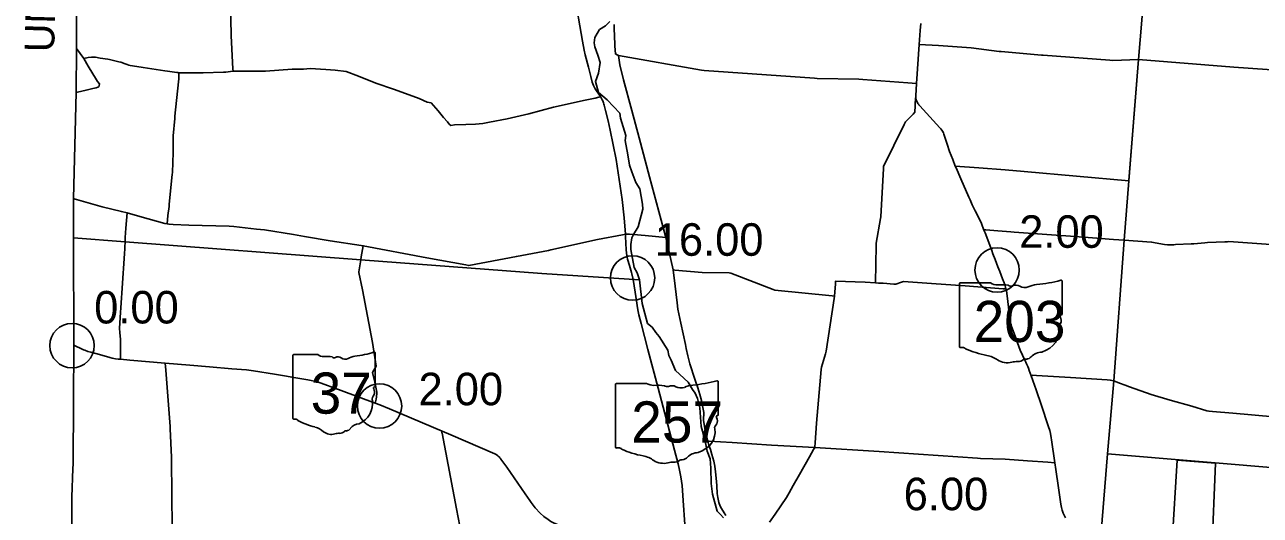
# Model space of a CAD drawing. Extents: x 1597222 to 1925846, y 496284 to 911751.
# Drawn here: x 1757865 to 1799698, y 847184 to 863780 of the extents above; entities that cross this region are included whole.
import ezdxf

# ---------------------------------------------------------------- set-up
doc = ezdxf.new("R2010")
doc.units = 0
for name, color, linetype in [('Default', 7, 'Continuous'), ('GM_X_Adjacent_County_Text', 7, 'Continuous'), ('GM_X_Corporation', 7, 'Continuous'), ('GM_X_County', 7, 'Continuous'), ('GM_X_County_Road', 7, 'Continuous'), ('GM_X_State_Route', 7, 'Continuous'), ('GM_X_State_Shield', 7, 'Continuous'), ('GM_X_Township', 7, 'Continuous'), ('GM_X_Township_Road', 7, 'Continuous')]:
    doc.layers.add(name, color=color, linetype=linetype)

msp = doc.modelspace()

# ---------------------------------------------------------------- linework, layer by layer
at = {"layer": 'Default'}
for centre in [(1778447, 855213), (1790786, 855482), (1759467, 852923), (1759467, 852923), (1769878, 850881)]:
    msp.add_circle(centre, 750, dxfattribs=at)
at = {"layer": 'GM_X_Corporation'}
msp.add_lwpolyline([(1796540, 843550), (1796878, 849051), (1798177, 848946), (1798053, 845944)], dxfattribs=at)
at = {"layer": 'GM_X_County'}
msp.add_lwpolyline([(1780889, 810163), (1780755, 818148), (1779378, 818146), (1775121, 818204), (1771439, 818234), (1765188, 818306), (1763158, 818312), (1762137, 818333), (1759879, 818354), (1759498, 818358), (1759475, 820549), (1759482, 825563), (1759416, 832152), (1759463, 844341), (1759463, 847793), (1759489, 848768), (1759505, 848913), (1759514, 851039), (1759526, 852942), (1759514, 856565), (1759518, 857896), (1759604, 861482), (1759615, 862978), (1759631, 865937)], dxfattribs=at)
at = {"layer": 'GM_X_County_Road'}
for points in [[(1779569, 856584), (1779019, 858639), (1778669, 859959), (1778417, 860876), (1778136, 861918), (1778010, 862427), (1777970, 862741)], [(1777970, 862741), (1780778, 862248), (1780868, 862232), (1784609, 861971), (1784696, 861964), (1786106, 861939), (1786241, 861929)], [(1786241, 861929), (1787766, 861819), (1788057, 861796)], [(1786675, 855044), (1786697, 856311), (1786698, 856387), (1786835, 857221), (1786845, 857279), (1786936, 858914), (1786940, 858987), (1787642, 860408), (1787683, 860493), (1787941, 860759), (1788006, 860826), (1788012, 861039), (1788018, 861131), (1788033, 861371)], [(1759518, 857896), (1759574, 857878), (1759613, 857869), (1760488, 857624), (1761137, 857456), (1761330, 857415)], [(1761330, 857415), (1761757, 857293), (1762604, 857057), (1762687, 857045), (1762755, 857030), (1762889, 857019), (1763416, 856999), (1764783, 856969), (1764940, 856958), (1765711, 856869), (1765986, 856836), (1766962, 856678), (1767342, 856615), (1768207, 856468), (1769260, 856311), (1769327, 856301), (1771485, 855899), (1771485, 855899)], [(1774515, 855940), (1775597, 856145), (1775681, 856161), (1777256, 856513), (1778103, 856674), (1778201, 856693), (1778256, 856697), (1778340, 856696), (1778464, 856683)], [(1778464, 856683), (1778481, 856682), (1778870, 856644), (1779569, 856584)], [(1779821, 855489), (1779569, 856584)], [(1771485, 855899), (1772805, 855652), (1772899, 855634), (1774513, 855940), (1774515, 855940)], [(1779821, 855489), (1779879, 855478), (1780796, 855402), (1781715, 855381), (1781774, 855378), (1783200, 854819), (1783259, 854796), (1785203, 854604), (1785283, 854596)], [(1783085, 846950), (1783272, 847226), (1783653, 847787), (1783748, 847942), (1783883, 848187), (1784102, 848564), (1784433, 849156), (1784568, 849404), (1784612, 849472), (1784619, 849495), (1784625, 849639), (1784668, 850295), (1784833, 852121), (1784839, 852194), (1784977, 852649), (1785005, 852740), (1785271, 854516), (1785283, 854596), (1785312, 855017), (1785318, 855106), (1786321, 855070), (1786675, 855044), (1786776, 855041), (1786778, 855041)], [(1786778, 855041), (1786924, 855037), (1787292, 855007), (1787356, 855002), (1787555, 855074), (1787618, 855096), (1788721, 855019), (1789216, 854979), (1789701, 854941), (1790989, 854849), (1791087, 854843)], [(1764156, 832620), (1763784, 836032), (1763776, 836097), (1763123, 841759), (1763037, 842583), (1762977, 843169), (1762897, 844278), (1762874, 844646), (1762856, 846750), (1762837, 849052), (1762835, 849154), (1762790, 850103), (1762786, 850187), (1762639, 852096), (1762618, 852326)], [(1773032, 837243), (1772998, 837442), (1772959, 837683), (1772924, 837925), (1772923, 837966), (1772930, 838064), (1773454, 841640), (1773504, 841940), (1773503, 842000), (1773497, 842064), (1773475, 842168), (1773363, 842728), (1773117, 844144), (1772881, 845349), (1772483, 847403), (1771993, 849965), (1771991, 849978), (1771991, 849991), (1771992, 850005), (1771995, 850019), (1771999, 850032)]]:
    msp.add_lwpolyline(points, dxfattribs=at)
at = {"layer": 'GM_X_State_Route'}
for points in [[(1780214, 846871), (1780156, 847683), (1780119, 848192), (1780103, 848341), (1780082, 848490), (1780037, 848711), (1779990, 848921), (1779866, 849386), (1779314, 851479), (1778967, 852787), (1778849, 853232), (1778732, 853677), (1778659, 853968), (1778625, 854134), (1778535, 854732), (1778466, 855163), (1778422, 855348), (1778404, 855403), (1778338, 855632), (1778279, 855845), (1778264, 855913), (1778254, 855963), (1778240, 856063), (1778232, 856164), (1778207, 856610), (1778201, 856693), (1778158, 857245), (1778089, 857871), (1777889, 859222), (1777685, 860217), (1777620, 860525), (1777532, 860880), (1777486, 861060), (1777476, 861098), (1777464, 861135), (1777451, 861171), (1777436, 861207), (1777419, 861242), (1777383, 861311), (1777355, 861355), (1777221, 861539), (1777176, 861609), (1777119, 861721), (1777075, 861838), (1777027, 862032), (1776950, 862347), (1776840, 862758), (1776807, 862917), (1776749, 863221), (1776467, 864856)], [(1793100, 847093), (1793045, 847210), (1793027, 847252), (1793013, 847289), (1792991, 847355), (1792967, 847443), (1792946, 847558), (1792850, 848193), (1792784, 848652), (1792773, 848731), (1792740, 848959), (1792628, 849742), (1792619, 849803), (1792592, 849950), (1792568, 850047), (1792530, 850174), (1792441, 850445), (1792367, 850662), (1792285, 850899), (1792105, 851429), (1791940, 851905), (1791877, 852084), (1791846, 852163), (1791822, 852220), (1791780, 852313), (1791755, 852366), (1791702, 852474), (1791642, 852598), (1791571, 852765), (1791525, 852890), (1791444, 853113), (1791397, 853241), (1791277, 853572), (1791258, 853631), (1791244, 853685), (1791226, 853784), (1791205, 853939), (1791111, 854702), (1791100, 854784), (1791087, 854843), (1791073, 854900), (1791061, 854942), (1791021, 855052), (1790974, 855179), (1790879, 855426), (1790817, 855588), (1790721, 855839), (1790647, 856032), (1790607, 856138), (1790378, 856737), (1790341, 856833), (1790254, 857050), (1790190, 857197), (1790044, 857488), (1789945, 857688), (1789872, 857851), (1789828, 857951), (1789562, 858562), (1789490, 858725), (1789407, 858912), (1789372, 858995), (1789284, 859215), (1789180, 859492), (1789091, 859742), (1788985, 860077), (1788969, 860118), (1788940, 860175), (1788914, 860215), (1788880, 860256), (1788847, 860293), (1788174, 861037), (1788137, 861075), (1788121, 861096), (1788106, 861118), (1788089, 861147), (1788079, 861165), (1788068, 861189), (1788050, 861239), (1788039, 861291), (1788033, 861371), (1788057, 861796), (1788151, 863108), (1788185, 863584), (1788200, 863823)], [(1759526, 852942), (1759591, 852908), (1759768, 852824), (1759855, 852784), (1759903, 852765), (1760002, 852730), (1760102, 852701), (1760277, 852652), (1760476, 852596), (1760744, 852525), (1760828, 852502), (1760935, 852482), (1761034, 852468), (1761108, 852461), (1761421, 852437), (1762618, 852326), (1763459, 852257), (1764120, 852204), (1764882, 852142), (1765375, 852101), (1765612, 852072), (1766327, 851954), (1766657, 851900), (1766981, 851843), (1767455, 851763), (1767775, 851700), (1768574, 851406), (1769730, 850976), (1769888, 850917), (1770221, 850789), (1771999, 850032), (1772292, 849906), (1773777, 849265), (1773831, 849237), (1773877, 849206), (1773898, 849188), (1773937, 849150), (1773955, 849129), (1773972, 849107), (1773988, 849084), (1774185, 848807), (1774812, 847908), (1774968, 847684)], [(1774968, 847684), (1775017, 847613), (1775152, 847432), (1775319, 847250), (1775446, 847139), (1775582, 847039), (1775677, 846979), (1775773, 846927), (1775925, 846858), (1776029, 846819), (1776243, 846761), (1776454, 846715), (1776476, 846710)]]:
    msp.add_lwpolyline(points, dxfattribs=at)
at = {"layer": 'GM_X_State_Shield'}
for p, q in [((1792989, 853994), (1792989, 855099)), ((1792989, 853994), (1792989, 855099)), ((1789509, 855011), (1789509, 852897)), ((1789509, 855011), (1789509, 852897)), ((1790562, 855047), (1789543, 855047)), ((1790562, 855047), (1789543, 855047)), ((1792989, 853994), (1792989, 853994)), ((1792989, 853994), (1792989, 853994)), ((1766947, 852586), (1766947, 850473)), ((1766947, 852586), (1766947, 850473)), ((1767790, 852623), (1766974, 852623)), ((1767790, 852623), (1766974, 852623)), ((1769731, 851569), (1769731, 852675)), ((1769731, 851569), (1769731, 852675)), ((1769731, 851570), (1769731, 851569)), ((1769731, 851570), (1769731, 851569)), ((1777866, 851609), (1777866, 849496)), ((1777866, 851609), (1777866, 849496)), ((1778920, 851646), (1777901, 851646)), ((1778920, 851646), (1777901, 851646)), ((1781347, 850593), (1781347, 851698)), ((1781347, 850593), (1781347, 851698)), ((1781346, 850593), (1781347, 850593)), ((1781346, 850593), (1781347, 850593))]:
    msp.add_line(p, q, dxfattribs=at)
for centre, radius, start, end in [((1766979, 852591), 32.3, 98.1301, 188.1301), ((1766979, 852591), 32.3, 98.1301, 188.1301), ((1767984, 852868), 313, 231.6195, 271.1119), ((1767984, 852868), 313, 231.6195, 271.1119), ((1768088, 851436), 1123, 80.4867, 94.9883), ((1768088, 851436), 1123, 80.4867, 94.9883), ((1769116, 851977), 594, 97.3462, 120.7689), ((1769116, 851977), 594, 97.3462, 120.7689), ((1768739, 855504), 2953, 275.8445, 288.9065), ((1768739, 855504), 2953, 275.8445, 288.9065), ((1769700, 852679), 31, 351.8621, 97.738), ((1769700, 852679), 31, 351.8621, 97.738), ((1768343, 852602), 90.3, 219.7921, 297.1024), ((1768343, 852602), 90.3, 219.7921, 297.1024), ((1768475, 852357), 188, 54.4667, 119.1411), ((1768475, 852357), 188, 54.4667, 119.1411), ((1768717, 852692), 226, 233.8562, 294.8282), ((1768717, 852692), 226, 233.8562, 294.8282), ((1769724, 851488), 48, 107.944, 210.337), ((1769724, 851488), 48, 107.944, 210.337), ((1769419, 851349), 288, 340.033, 23.6496), ((1769419, 851349), 288, 340.033, 23.6496), ((1769698, 851565), 33.2, 289.6038, 7.7341), ((1769698, 851565), 33.2, 289.6038, 7.7341), ((1768905, 850966), 739, 292.3089, 8.9858), ((1768905, 850966), 739, 292.3089, 8.9858), ((1769842, 851107), 210, 136.8065, 186.9296), ((1769842, 851107), 210, 136.8065, 186.9296), ((1766979, 850468), 32.5, 171.9584, 258.3066), ((1766979, 850468), 32.5, 171.9584, 258.3066), ((1766984, 850684), 248, 267.339, 280.6039), ((1766984, 850684), 248, 267.339, 280.6039), ((1767035, 850351), 89.5, 29.7484, 93.2717), ((1767035, 850351), 89.5, 29.7484, 93.2717), ((1768165, 852250), 2132, 240.4129, 257.1985), ((1768165, 852250), 2132, 240.4129, 257.1985), ((1767530, 849523), 667, 47.1842, 75.836), ((1767530, 849523), 667, 47.1842, 75.836), ((1768704, 850268), 239, 282.8732, 323.2771), ((1768704, 850268), 239, 282.8732, 323.2771), ((1769216, 849880), 404, 94.4031, 142.5768), ((1769216, 849880), 404, 94.4031, 142.5768), ((1768251, 850340), 423, 230.7004, 286.2918), ((1768251, 850340), 423, 230.7004, 286.2918), ((1768496, 849610), 348, 85.6951, 111.2099), ((1768496, 849610), 348, 85.6951, 111.2099), ((1768527, 850182), 226, 268.777, 315.5493), ((1768527, 850182), 226, 268.777, 315.5493), ((1768731, 849978), 63.5, 65.7517, 132.6484), ((1768731, 849978), 63.5, 65.7517, 132.6484)]:
    msp.add_arc(centre, radius, start, end, dxfattribs=at)
for centre, major_axis, start_param, end_param in [((1791749, 857928), (3691, 0), 4.814394, 5.042369), ((1791749, 857928), (3691, 0), 4.814394, 5.042369), ((1792950, 855104), (38.7, 0), 6.141152, 7.989035), ((1792950, 855104), (38.7, 0), 6.141152, 7.989035), ((1789548, 855015), (40.3, 0), 1.712693, 3.28349), ((1789548, 855015), (40.3, 0), 1.712693, 3.28349), ((1790805, 855292), (391, 0), 4.042523, 4.731795), ((1790805, 855292), (391, 0), 4.042523, 4.731795), ((1790935, 853860), (1404, 0), 1.404758, 1.657858), ((1790935, 853860), (1404, 0), 1.404758, 1.657858), ((1791253, 855026), (113, 0), 3.836095, 5.185415), ((1791253, 855026), (113, 0), 3.836095, 5.185415), ((1791419, 854782), (235, 0), 0.950623, 2.079405), ((1791419, 854782), (235, 0), 0.950623, 2.079405), ((1791722, 855117), (282, 0), 4.081561, 5.145723), ((1791722, 855117), (282, 0), 4.081561, 5.145723), ((1792220, 854401), (743, 0), 1.699011, 2.107814), ((1792220, 854401), (743, 0), 1.699011, 2.107814), ((1792980, 853913), (60, 0), 1.883978, 3.671073), ((1792980, 853913), (60, 0), 1.883978, 3.671073), ((1792599, 853773), (360, 0), 5.934695, 6.695948), ((1792599, 853773), (360, 0), 5.934695, 6.695948), ((1792948, 853990), (41.5, 0), 5.05454, 6.418171), ((1792948, 853990), (41.5, 0), 5.05454, 6.418171), ((1791956, 853391), (923, 0), 5.101752, 6.440018), ((1791956, 853391), (923, 0), 5.101752, 6.440018), ((1793128, 853531), (262, 0), 2.387724, 3.262537), ((1793128, 853531), (262, 0), 2.387724, 3.262537), ((1789549, 852893), (40.7, 0), 3.00124, 4.508301), ((1789549, 852893), (40.7, 0), 3.00124, 4.508301), ((1789555, 853109), (310, 0), 4.665946, 4.897461), ((1789555, 853109), (310, 0), 4.665946, 4.897461), ((1789619, 852775), (112, 0), 0.519207, 1.627899), ((1789619, 852775), (112, 0), 0.519207, 1.627899), ((1791032, 854674), (2665, 0), 4.195997, 4.488961), ((1791032, 854674), (2665, 0), 4.195997, 4.488961), ((1790237, 851948), (834, 0), 0.823519, 1.323587), ((1790237, 851948), (834, 0), 0.823519, 1.323587), ((1792345, 852304), (506, 0), 1.647645, 2.488434), ((1792345, 852304), (506, 0), 1.647645, 2.488434), ((1791139, 852765), (529, 0), 4.026481, 4.996735), ((1791139, 852765), (529, 0), 4.026481, 4.996735), ((1791445, 852034), (435, 0), 1.495662, 1.94098), ((1791445, 852034), (435, 0), 1.495662, 1.94098), ((1791483, 852607), (282, 0), 4.691044, 5.507374), ((1791483, 852607), (282, 0), 4.691044, 5.507374), ((1791739, 852402), (79.4, 0), 1.147584, 2.315152), ((1791739, 852402), (79.4, 0), 1.147584, 2.315152), ((1791705, 852692), (298, 0), 4.937069, 5.64225), ((1791705, 852692), (298, 0), 4.937069, 5.64225), ((1780107, 854527), (3691, 0), 4.814394, 5.042369), ((1780107, 854527), (3691, 0), 4.814394, 5.042369), ((1781308, 851703), (38.7, 0), 6.141152, 7.989035), ((1781308, 851703), (38.7, 0), 6.141152, 7.989035), ((1777906, 851614), (40.3, 0), 1.712693, 3.28349), ((1777906, 851614), (40.3, 0), 1.712693, 3.28349), ((1779162, 851891), (391, 0), 4.042523, 4.731795), ((1779162, 851891), (391, 0), 4.042523, 4.731795), ((1779292, 850459), (1404, 0), 1.404758, 1.657858), ((1779292, 850459), (1404, 0), 1.404758, 1.657858), ((1779611, 851625), (113, 0), 3.836095, 5.185415), ((1779611, 851625), (113, 0), 3.836095, 5.185415), ((1779777, 851381), (235, 0), 0.950623, 2.079405), ((1779777, 851381), (235, 0), 0.950623, 2.079405), ((1780079, 851716), (282, 0), 4.081561, 5.145723), ((1780079, 851716), (282, 0), 4.081561, 5.145723), ((1780578, 851000), (743, 0), 1.699011, 2.107814), ((1780578, 851000), (743, 0), 1.699011, 2.107814), ((1781338, 850511), (60, 0), 1.883978, 3.671073), ((1781338, 850511), (60, 0), 1.883978, 3.671073), ((1780956, 850372), (360, 0), 5.934695, 6.695948), ((1780956, 850372), (360, 0), 5.934695, 6.695948), ((1781305, 850588), (41.5, 0), 5.05454, 6.418171), ((1781305, 850588), (41.5, 0), 5.05454, 6.418171), ((1780314, 849989), (923, 0), 5.101752, 6.440018), ((1780314, 849989), (923, 0), 5.101752, 6.440018), ((1781485, 850130), (262, 0), 2.387724, 3.262537), ((1781485, 850130), (262, 0), 2.387724, 3.262537), ((1777906, 849491), (40.7, 0), 3.00124, 4.508301), ((1777906, 849491), (40.7, 0), 3.00124, 4.508301), ((1777913, 849708), (310, 0), 4.665946, 4.897461), ((1777913, 849708), (310, 0), 4.665946, 4.897461), ((1777976, 849374), (112, 0), 0.519207, 1.627899), ((1777976, 849374), (112, 0), 0.519207, 1.627899), ((1779389, 851273), (2665, 0), 4.195997, 4.488961), ((1779389, 851273), (2665, 0), 4.195997, 4.488961), ((1780703, 848903), (506, 0), 1.647645, 2.488434), ((1780703, 848903), (506, 0), 1.647645, 2.488434), ((1778595, 848547), (834, 0), 0.823519, 1.323587), ((1778595, 848547), (834, 0), 0.823519, 1.323587), ((1779497, 849364), (529, 0), 4.026481, 4.996735), ((1779497, 849364), (529, 0), 4.026481, 4.996735), ((1779802, 848633), (435, 0), 1.495662, 1.94098), ((1779802, 848633), (435, 0), 1.495662, 1.94098), ((1779841, 849205), (282, 0), 4.691044, 5.507374), ((1779841, 849205), (282, 0), 4.691044, 5.507374), ((1780096, 849001), (79.4, 0), 1.147584, 2.315152), ((1780096, 849001), (79.4, 0), 1.147584, 2.315152), ((1780062, 849291), (298, 0), 4.937069, 5.64225), ((1780062, 849291), (298, 0), 4.937069, 5.64225)]:
    msp.add_ellipse(centre, major_axis=major_axis, ratio=0.8, start_param=start_param, end_param=end_param, dxfattribs=at)
at = {"layer": 'GM_X_Township'}
for points in [[(1796250, 870609), (1795573, 862604), (1795247, 858499), (1795090, 856488), (1794738, 851729), (1794528, 849265), (1794250, 845913)], [(1781519, 847094), (1781420, 847210), (1781308, 847324), (1781148, 847901), (1781109, 848257), (1781090, 848776), (1781068, 849092), (1780971, 849357), (1780904, 849691), (1780816, 850027), (1780762, 850186), (1780725, 850820), (1780641, 851138), (1780564, 851310), (1780471, 851440), (1780333, 851692), (1779900, 852077), (1779756, 852426), (1779678, 852587), (1779637, 852766), (1779349, 853231), (1779232, 853362), (1779109, 853545), (1778954, 853677), (1778765, 854353), (1778678, 855150), (1778601, 855389), (1778502, 855569), (1778390, 856177), (1778385, 856340), (1778415, 856566), (1778481, 856682), (1778631, 856948), (1778790, 857538), (1778777, 857706), (1778686, 858229), (1778551, 858440), (1778417, 858800), (1778344, 859030), (1778284, 859383), (1778195, 859863), (1778212, 860031), (1778036, 860617), (1778010, 860785), (1777585, 861235), (1777295, 861489), (1777189, 861855), (1777288, 862139), (1777344, 862501), (1777271, 862751), (1777172, 863030), (1777146, 863168), (1777170, 863351), (1777325, 863614), (1777527, 863741), (1777673, 863892)], [(1778678, 855150), (1775377, 855361), (1769242, 855826), (1761265, 856432), (1759514, 856565)], [(1794528, 849265), (1800736, 848740), (1801113, 848728), (1805038, 848430), (1809012, 848241), (1810328, 848152), (1816586, 847751), (1820950, 847472)]]:
    msp.add_lwpolyline(points, dxfattribs=at)
at = {"layer": 'GM_X_Township_Road'}
for points in [[(1795573, 862604), (1796250, 870609)], [(1764837, 864452), (1764833, 864303), (1764859, 863478), (1764860, 863401), (1764913, 862293), (1764917, 862205)], [(1777970, 862741), (1777923, 862765), (1777865, 862795), (1777848, 863058), (1777843, 863124), (1777826, 863652), (1777823, 863735), (1777822, 863788)], [(1788151, 863108), (1788798, 863076), (1789909, 862999), (1790859, 862876), (1790920, 862871), (1792288, 862753), (1792341, 862749), (1794605, 862578), (1794706, 862571), (1795573, 862604)], [(1759604, 861482), (1759656, 861496), (1759943, 861570), (1760085, 861602), (1760176, 861624), (1760279, 861650), (1760337, 861664), (1760377, 861684), (1760387, 861726), (1760397, 861779), (1760334, 861863), (1760297, 861913), (1760017, 862374), (1759867, 862636), (1759615, 862978)], [(1759867, 862636), (1760013, 862666), (1760130, 862682), (1760151, 862684), (1760179, 862685), (1760207, 862685), (1760234, 862684), (1760262, 862681), (1760414, 862652), (1760683, 862611), (1760740, 862599), (1761049, 862530), (1761122, 862513), (1761270, 862456), (1761337, 862431), (1761387, 862415), (1761439, 862399), (1761804, 862342), (1761878, 862331), (1762609, 862220), (1762700, 862206), (1763014, 862165), (1763041, 862161)], [(1795248, 858510), (1795573, 862604)], [(1795573, 862604), (1795573, 862604), (1798801, 862345), (1799934, 862267), (1800231, 862253), (1800471, 862240)], [(1763041, 862161), (1763047, 862161), (1763081, 862156), (1763820, 862158), (1763909, 862158), (1764595, 862177), (1764674, 862179), (1764832, 862196), (1764917, 862205)], [(1764917, 862205), (1766017, 862209), (1766916, 862272), (1767304, 862272), (1767528, 862298), (1768057, 862265), (1768381, 862241), (1768751, 862199), (1769163, 862037), (1769751, 861801), (1770349, 861595), (1770876, 861403), (1771222, 861283), (1771494, 861163), (1771624, 861139), (1771860, 860864), (1772046, 860638), (1772174, 860498), (1772234, 860420), (1772290, 860376), (1772412, 860388), (1772798, 860402), (1773128, 860421), (1773381, 860443), (1773597, 860481), (1774197, 860598), (1774937, 860763), (1775772, 860991), (1776842, 861229), (1777174, 861301), (1777307, 861331), (1777355, 861355)], [(1762687, 857045), (1762714, 857325), (1762752, 857634), (1762759, 857710), (1762857, 858709), (1762863, 858776), (1762892, 859462), (1762895, 859538), (1762893, 859960), (1762893, 860024), (1762945, 860602), (1762953, 860690), (1763076, 861845), (1763087, 861944), (1763086, 862049), (1763085, 862132)], [(1789372, 858995), (1790171, 858935), (1791063, 858867), (1791706, 858811), (1795247, 858499)], [(1795090, 856488), (1795247, 858499), (1795248, 858510)], [(1761259, 856255), (1761265, 856432), (1761271, 856584), (1761290, 856895), (1761330, 857415)], [(1790341, 856833), (1790361, 856840), (1790407, 856844), (1790813, 856811), (1791251, 856773), (1791363, 856765), (1792476, 856688), (1792792, 856660), (1793270, 856623), (1794021, 856567), (1794727, 856514), (1795090, 856488)], [(1795090, 856488), (1796016, 856428), (1796449, 856346), (1796551, 856339), (1796604, 856337), (1796665, 856335), (1796771, 856339), (1796829, 856341), (1797357, 856367), (1797448, 856371), (1797816, 856403), (1797914, 856411), (1798495, 856434), (1798591, 856437), (1798633, 856451), (1800371, 856321), (1800474, 856313), (1801054, 856281), (1801112, 856277), (1801481, 856249), (1801549, 856244)], [(1761108, 852461), (1761107, 852748), (1761105, 852938), (1761109, 853081), (1761106, 853127), (1761082, 853368), (1761079, 853503), (1761097, 853880), (1761164, 854868), (1761246, 856040), (1761257, 856202), (1761259, 856255)], [(1769179, 855423), (1769242, 855826), (1769258, 855928), (1769327, 856301)], [(1781600, 847179), (1781548, 847266), (1781457, 847417), (1781415, 847493), (1781364, 847615), (1781331, 847781), (1781312, 847922), (1781300, 848183), (1781284, 848331), (1781251, 848655), (1781227, 848848), (1781196, 849012), (1781134, 849243), (1781087, 849407), (1781028, 849552), (1780989, 849690), (1780954, 849823), (1780912, 849990), (1780877, 850183), (1780851, 850403), (1780857, 850663), (1780848, 850718), (1780780, 851064), (1780725, 851272), (1780652, 851494), (1780597, 851656), (1780552, 851786), (1780381, 852308), (1780317, 852579), (1780262, 852823), (1780236, 852965), (1780083, 853686), (1779980, 854155), (1779958, 854372), (1779890, 854936), (1779821, 855489)], [(1769730, 850976), (1769768, 851110), (1769780, 851187), (1769790, 851318), (1769788, 851354), (1769715, 851685), (1769645, 852012), (1769767, 852228), (1769641, 853033), (1769298, 854816), (1769176, 855403), (1769177, 855414), (1769179, 855423)], [(1791940, 851905), (1791969, 851918), (1791991, 851922), (1792120, 851917), (1792308, 851904), (1793274, 851846), (1794516, 851767), (1794619, 851757), (1794724, 851732)], [(1794724, 851732), (1794738, 851729), (1794935, 851656), (1795122, 851581), (1795265, 851527), (1796002, 851268), (1796641, 851079), (1797379, 850870), (1797893, 850723), (1797966, 850705), (1798085, 850695), (1798763, 850635), (1800156, 850514), (1800763, 850469), (1801182, 850439), (1801250, 850449)], [(1780989, 849690), (1781043, 849696), (1781425, 849669), (1781815, 849644), (1783144, 849553), (1784612, 849472)], [(1784612, 849472), (1786799, 849340), (1790129, 849115), (1790221, 849109), (1791065, 849081), (1791820, 849028), (1792506, 848978), (1792740, 848959)]]:
    msp.add_lwpolyline(points, dxfattribs=at)

# ---------------------------------------------------------------- texts
at = {"layer": 'Default'}
for s, p in [('2.00', (1791536, 856232)), ('16.00', (1779197, 855963)), ('0.00', (1760217, 853673)), ('2.00', (1771198, 850906)), ('6.00', (1787624, 847355))]:
    msp.add_text(s, height=1100, dxfattribs=at).set_placement(p)
at = {"layer": 'GM_X_Adjacent_County_Text'}
msp.add_text('UNION COUNTY', height=1000, rotation=88.7699, dxfattribs=at).set_placement((1758862, 862842))
at = {"layer": 'GM_X_State_Shield'}
for s, p in [('203', (1789994, 853046)), ('203', (1789994, 853046)), ('37', (1767548, 850622)), ('37', (1767548, 850622)), ('257', (1778402, 849645)), ('257', (1778402, 849645))]:
    msp.add_text(s, height=1392.2, dxfattribs=at).set_placement(p)

doc.saveas('drawing.dxf')
